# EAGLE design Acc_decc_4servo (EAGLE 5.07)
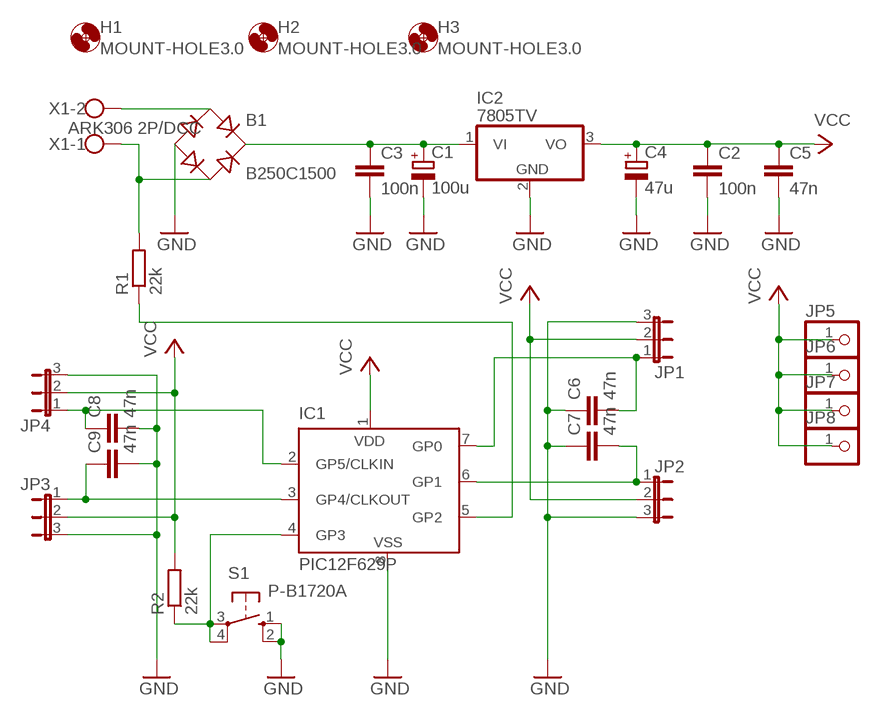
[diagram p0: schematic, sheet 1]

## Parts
B1  B250C1500  RB1A  [RB1A]
C1  100u  CPOL-EUE2,5-6E  [E2,5-6E]
C2  100n  C-EU050-024X044  [C050-024X044]
C3  100n  C-EU050-024X044  [C050-024X044]
C4  47u  CPOL-EUE2,5-6E  [E2,5-6E]
C5  47n  C-EU050-024X044  [C050-024X044]
C6  47n  C-EU050-024X044  [C050-024X044]
C7  47n  C-EU050-024X044  [C050-024X044]
C8  47n  C-EU050-024X044  [C050-024X044]
C9  47n  C-EU050-024X044  [C050-024X044]
H1  MOUNT-HOLE3.0  [3,0]
H2  MOUNT-HOLE3.0  [3,0]
H3  MOUNT-HOLE3.0  [3,0]
IC1  PIC12F629P  [DIL8]
IC2  7805TV  [TO220V]
JP1  JP2E  [JP2]
JP2  JP2E  [JP2]
JP3  JP2E  [JP2]
JP4  JP2E  [JP2]
JP5  PINHD-1X1  [1X01]
JP6  PINHD-1X1  [1X01]
JP7  PINHD-1X1  [1X01]
JP8  PINHD-1X1  [1X01]
R1  22k  R-EU_0207/10  [0207/10]
R2  22k  R-EU_0207/10  [0207/10]
S1  P-B1720A  10-XX  [B3F-10XX]
X1  ARK306 2P/DCC  W237-102  [W237-102]

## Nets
GND: B1.- C1.- C2.2 C3.2 C4.- C5.2 C6.1 C7.1 C8.2 C9.2 IC1.8(VSS) IC2.2(GND) JP1.3 JP2.3 JP3.3 JP4.3 S1.1(S) S1.2(S1)
N$1: B1.AC1 X1.2
N$2: B1.AC2 R1.2 X1.1
N$3: B1.+ C1.+ C3.1 IC2.1(VI)
N$4: IC1.5(GP2) R1.1
N$5: IC1.4(GP3) R2.1 S1.3(P) S1.4(P1)
N$6: C9.1 IC1.3(GP4/CLKOUT) JP3.1
N$7: C8.1 IC1.2(GP5/CLKIN) JP4.1
N$8: C6.2 IC1.7(GP0) JP1.1
N$9: C7.2 IC1.6(GP1) JP2.1
VCC: C2.1 C4.+ C5.1 IC1.1(VDD) IC2.3(VO) JP1.2 JP2.2 JP3.2 JP4.2 JP5.1 JP6.1 JP7.1 JP8.1 R2.2

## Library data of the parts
B1 = rectifier:RB1A: RECTIFIER 1 A
C1 C4 = rcl:CPOL-EU: POLARIZED CAPACITOR, European symbol
C2 C3 C5-C9 = rcl:C-EU: CAPACITOR, European symbol
H1-H3 = holes:MOUNT-HOLE: MOUNTING HOLE with drill center marker
IC1 = microchip:PIC12F6*: Data Sheet 8-Pin FLASH-Based 8-Bit CMOS Microcontrollers Source: http://www.microchip.com .. 41190c.pdf
IC2 = linear:78*: Positive VOLTAGE REGULATOR Source: http://cache.national.com/ds/LM/LM78L05.pdf http://www.fairchildsemi.com/ds/LM/LM7805.pdf
JP1-JP4 = jumper:JP2E: JUMPER
JP5-JP8 = pinhead:PINHD-1X1: PIN HEADER
R1 R2 = rcl:R-EU_: RESISTOR, European symbol
S1 = switch-omron:10-XX: OMRON SWITCH
X1 = con-wago-500:W237-102: WAGO SCREW CLAMP

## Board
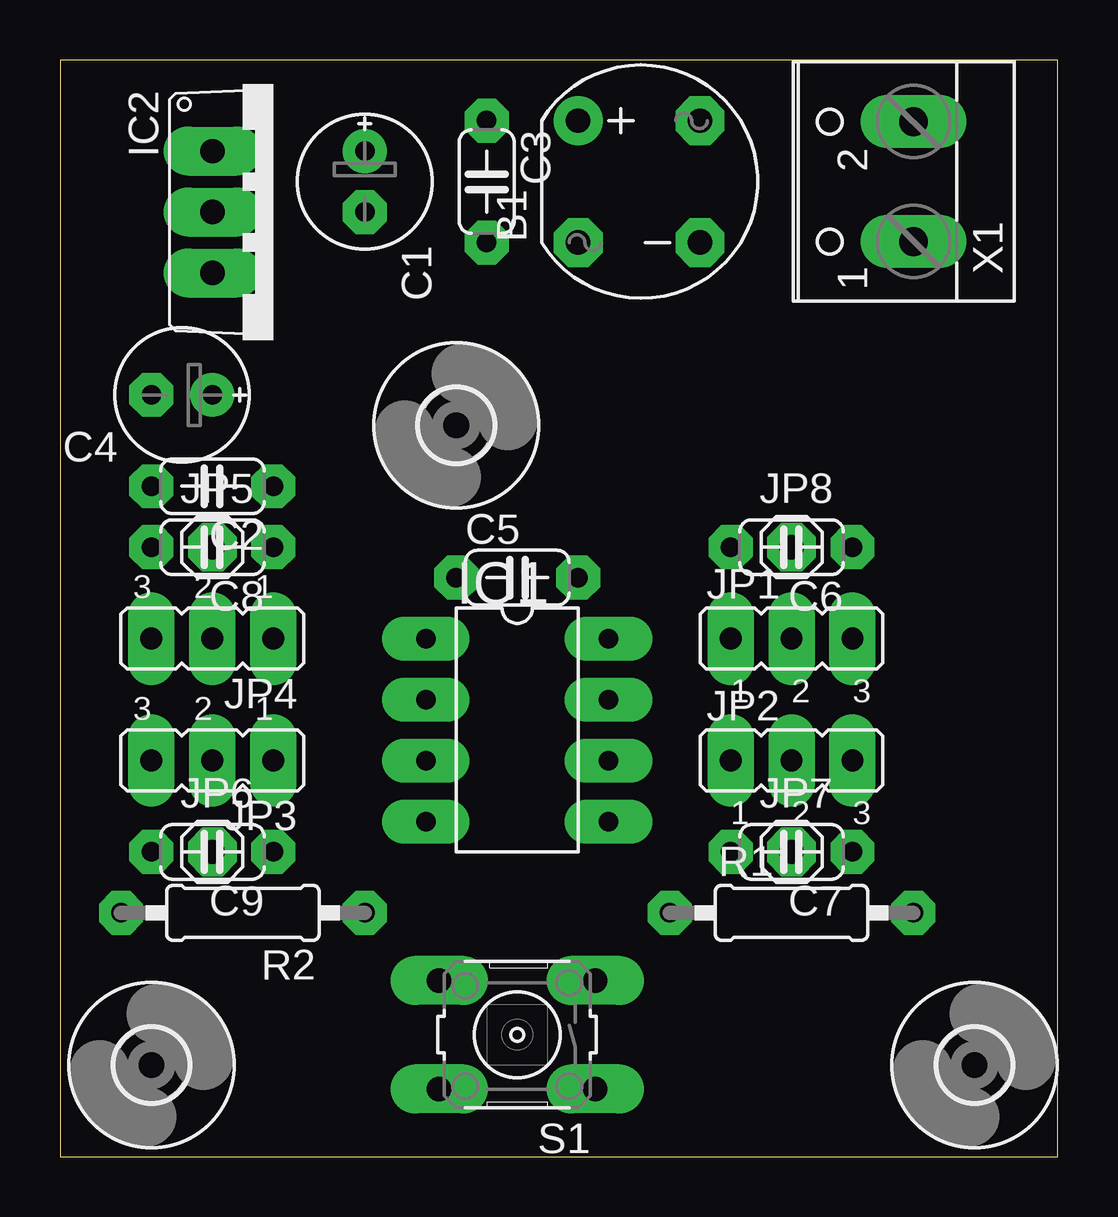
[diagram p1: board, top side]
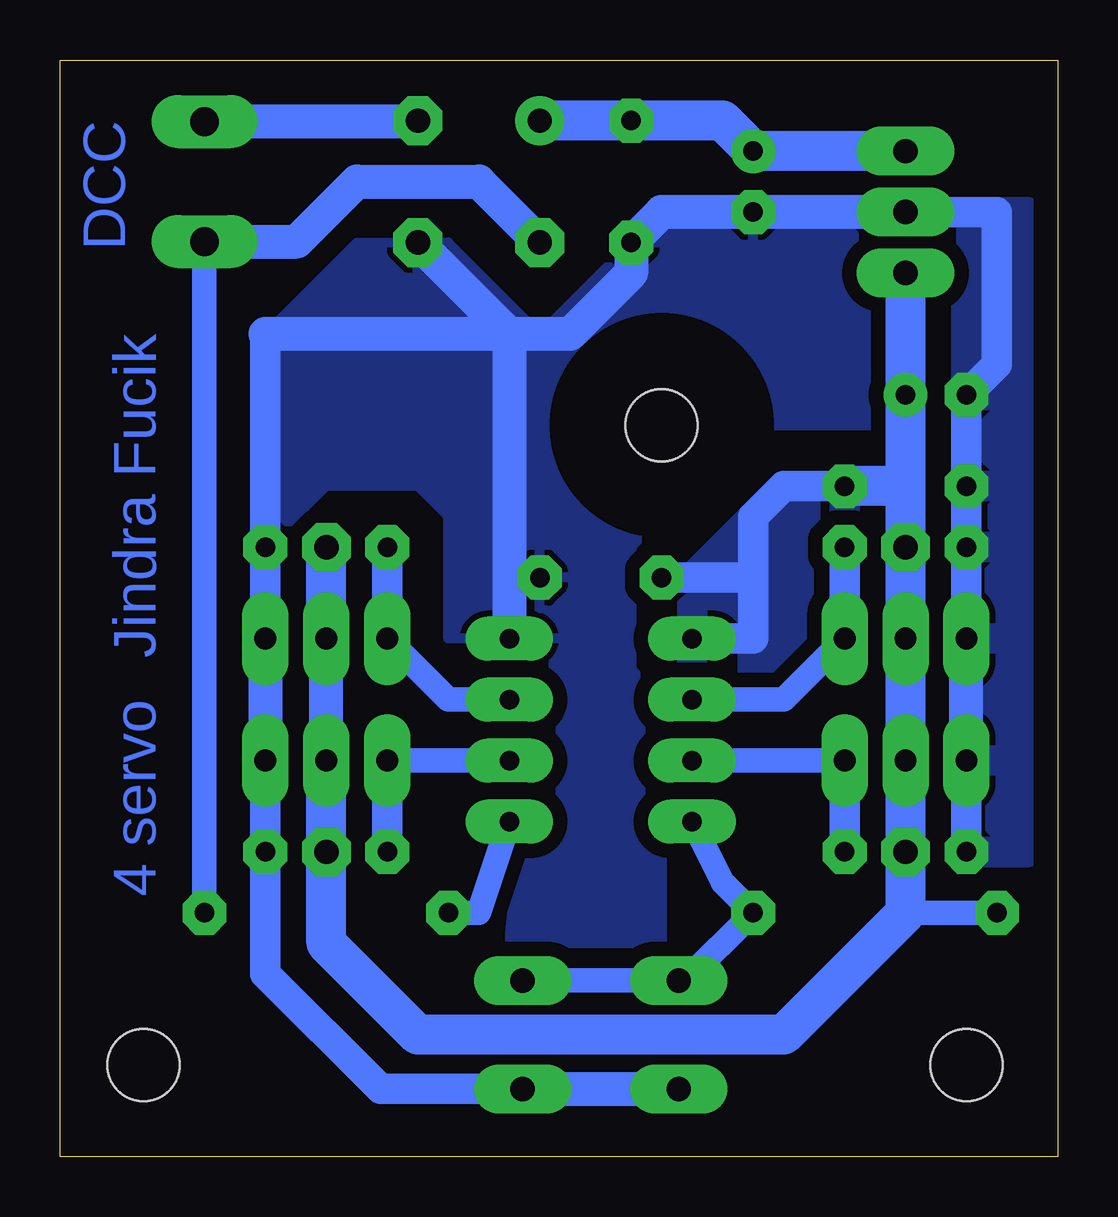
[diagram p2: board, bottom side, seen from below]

Size 41.58 x 45.71 mm. Coordinates in mm from the lower left corner, seen from the top.
Outline: 0,0 41.58,0 41.58,45.71 0,45.71 0,0
Copper layers (1*16): Top 0.035mm / dielectric 1.5mm / Bottom 0.035mm
Design rules "default *": minimum track width 10mil, minimum drill 24mil, track to track 8mil, track to pad 8mil, pad to pad 8mil, via to via 8mil, smd to smd 8mil, copper to edge 40mil, drill to drill 8mil, minimum pad ring 20mil, minimum via ring 8mil, stop-mask expansion 4mil, vias tented up to drill 0mil, thermal gap 10mil

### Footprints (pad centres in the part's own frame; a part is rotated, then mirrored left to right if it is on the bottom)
RB1A = drill 1.016 round: + -2.54,2.54 | drill 1.016 octagon: - 2.54,-2.54; AC1 2.54,2.54; AC2 -2.54,-2.54
E2,5-6E = drill 0.813 pad 1.575 round: + -1.27,0 | drill 0.813 pad 1.575 octagon: - 1.27,0
C050-024X044 = drill 0.813 octagon: 1 -2.54,0; 2 2.54,0
3,0 = hole 3: 0,0
DIL8 = drill 0.813 long: 1 -3.81,-3.81; 2 -1.27,-3.81; 3 1.27,-3.81; 4 3.81,-3.81; 5 3.81,3.81; 6 1.27,3.81; 7 -1.27,3.81; 8 -3.81,3.81
TO220V = drill 1.016 long: 1 -2.54,-2.54; 2 0,-2.54; 3 2.54,-2.54
JP2 = drill 0.914 long: 1 -2.54,0; 2 0,0; 3 2.54,0
1X01 = drill 1.016 octagon: 1 0,0
0207/10 = drill 0.813 octagon: 1 -5.08,0; 2 5.08,0
B3F-10XX = drill 1.016 long: 1 -3.251,2.261; 2 3.251,2.261; 3 -3.251,-2.261; 4 3.251,-2.261
W237-102 = drill 1.194 long: 1 -2.5,-1.27; 2 2.5,-1.27

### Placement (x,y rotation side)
B1  24.13,40.64 0 top
C1  12.7,40.64 270 top
C2  6.35,27.94 180 top
C3  17.78,40.64 270 top
C4  5.08,31.75 180 top
C5  19.05,24.13 0 top
C6  30.48,25.4 180 top
C7  30.48,12.7 180 top
C8  6.35,25.4 180 top
C9  6.35,12.7 180 top
H1  3.81,3.81 0 top
H2  38.1,3.81 0 top
H3  16.51,30.48 0 top
IC1  19.05,17.78 270 top
IC2  8.89,39.37 270 top
JP1  30.48,21.59 0 top
JP2  30.48,16.51 0 top
JP3  6.35,16.51 180 top
JP4  6.35,21.59 180 top
JP5  6.35,25.4 0 top
JP6  6.35,12.7 0 top
JP7  30.48,12.7 0 top
JP8  30.48,25.4 0 top
R1  30.48,10.16 0 top
R2  7.62,10.16 180 top
S1  19.05,5.08 180 top
X1  34.29,40.64 90 top

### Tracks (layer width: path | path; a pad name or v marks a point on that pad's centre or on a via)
GND
  Bottom 0.813: 22.86,24.13 C5.2
  Bottom 1.27: S1.1 28.22,2.82 33.02,7.62 C7.1 JP2.3 | C9.2 JP3.3 | JP4.3 C8.2 C2.2 C4.- 2.54,33.02 2.54,39.37 IC2.2 | C6.1 JP1.3 33.02,34.29
  Bottom 1.422: IC2.2 C1.- 16.51,39.37 C3.2 17.78,36.83 20.32,34.29 22.86,34.29 | 22.86,34.29 B1.- | 22.86,34.29 22.86,24.13 IC1.8 | JP3.3 JP4.3 | JP1.3 JP2.3 | 22.86,34.29 33.02,34.29 | S1.2 S1.1 22.58,2.54
  pour Bottom (isolate 0.61): 6.35,39.37 6.35,30.48 12.7,30.48 17.78,25.4 17.78,20.32 16.51,19.05 16.51,8.89 22.86,8.89 21.59,21.59 25.4,21.59 25.4,26.67 26.67,27.94 30.48,27.94 33.02,25.4 33.02,34.29 29.21,38.1 25.4,38.1 21.59,34.29 16.51,39.37
  pour Bottom (isolate 0.61): 1.27,39.37 1.27,12.7 3.81,12.7 3.81,39.37
N$1
  Bottom 1.016: 26.67,43.14 B1.AC1
  Bottom 1.422: 26.67,43.14 X1.2
N$2
  Bottom 1.016: R1.2 X1.1
  Bottom 1.422: X1.1 31.71,38.14 29.21,40.64 24.13,40.64 B1.AC2
N$3
  Bottom 1.676: B1.+ C3.1 13.97,43.18 C1.+ IC2.1
N$4
  Bottom 1.016: R1.1 24.13,10.16 IC1.5
N$5
  Bottom 1.016: IC1.4 13.97,11.43 R2.1 15.52,7.34 S1.4 S1.3
N$6
  Bottom 1.016: JP3.1 IC1.3
  Bottom 1.27: C9.1 JP3.1
N$7
  Bottom 1.016: IC1.2 11.43,19.05 JP4.1
  Bottom 1.27: JP4.1 C8.1
N$8
  Bottom 1.016: IC1.7 25.4,19.05 JP1.1
  Bottom 1.27: JP1.1 C6.2
N$9
  Bottom 1.016: IC1.6 JP2.1
  Bottom 1.27: JP2.1 C7.2
VCC
  Bottom 1.016: R2.2 6.35,10.16
  Bottom 1.27: IC1.1 12.7,21.59 12.7,24.13 | 12.7,24.13 C5.1 | 12.7,24.13 12.7,26.67 11.43,27.94 C2.1
  Bottom 1.422: JP2.2 JP1.2
  Bottom 1.676: IC2.3 C4.+ 6.35,27.94 | 6.35,27.94 C2.1 | 6.35,27.94 JP5.1 JP4.2 JP3.2 JP6.1 6.35,10.16 11.43,5.08 26.67,5.08 30.48,8.89 JP7.1 JP2.2 | JP1.2 JP8.1
  pour Bottom (isolate 0.61): 8.89,27.94 11.43,27.94 15.24,24.13 15.24,20.32 10.16,20.32 8.89,21.59
(copper drawn outside any net)
  shapes: Bottom circle x2

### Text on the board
Bottom: DCC | Jindra Fucik | 4 servo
